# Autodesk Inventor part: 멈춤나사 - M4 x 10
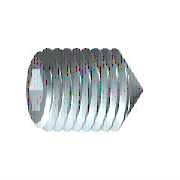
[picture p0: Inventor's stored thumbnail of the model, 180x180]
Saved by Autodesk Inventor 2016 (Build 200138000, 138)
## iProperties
Created: 2012-02
Part Number: 멈춤나사 - M4 x 10
Material: 강철, 연강
Description: 6각 소켓 머리 없는 멈춤 나사
Document SubType Name: Modeling
Standard: KS B 1028
Designer: mduedu
Standards Organization: KS
Language: ko-KR
Size Designation: 원추점 M4x10
Categories: <MemberInstance><Categories><Category DisplayName="조임쇠" InternalName="e4da775c-781d-43d5-af7c-5136215cf5a6" Mnemonic="FSTN"><Category DisplayName="볼트" InternalN
Density: 7.86 g/cm^3
Mass: 0.792069 g
Surface Area: 1.48192 cm^2
Volume: 0.100772 cm^3
Appearance: 강철
Author: mduedu
IsCustomPart: 1
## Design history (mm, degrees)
sketch "스케치1"
  geometry: L1 (0, 0)-(6.833, 0); L2 (10, 1.155)-(10, 2); L3 (10, 2)-(0, 2); L4 (10, 1.155)-(7.5, 1.155); L5 (7.5, 1.155)-(6.833, 0); L6 (0, -0.4)-(0, 2.4) reference; L7 (0, 2)-(0, 0)
  constraints: 13 end point, 3 parallel, 1 collinear, 1 perpendicular, 1 point on line
  dimensions: "d0" = 2.5 distance of L2.start L4.end (= INTI); "d1" = 60 deg angle of L5 L1; "d2" = 4 diameter of L3 L1 (= NND); "d3" = 2.3094 diameter of L4 L1 (= 1.1547 x SW); "d5" = 10 distance from line of L2 L3.end (= NLG)
revolve "본체" sketch "스케치1" stored, may be unused: angle "d6" = 90 deg
sketch "스케치2"
  geometry: L1 (-0.577, 1)-(0.577, 1); L2 (0.577, 1)-(1.155, 0); L3 (1.155, 0)-(0.577, -1); L4 (0.577, -1)-(-0.577, -1); L5 (-0.577, -1)-(-1.155, 0); L6 (-1.155, 0)-(-0.577, 1); 3 further points
  constraints: 12 end point, 1 coincident, 1 horizontal, 13 other
extrude "슬롯" join sketch "스케치2" taper "d7" = 0 deg; stored distance "d21" = 10
workaxis "Work Axis1"
workplane "Work Plane1"
sketch "스케치4"
  geometry: L1 (-5, 0.2)-(-3.2, 2) reference; L2 (-5, -0.2)-(-3.2, -2) reference; L3 (-3.2, 2)-(-5.2, 0); L4 (-3.2, -2)-(-5.2, 0); 2 further points
  constraints: 4 end point, 2 collinear, 1 coincident
body "Solid1"
feature "스레드" dims "d12" = 10 (= NLG), "d13" = 0
chamfer "모따기1" distance "d8" = 1.8 (computed from NND, SPD, FAWI); stored, may be unused: angle "d9" = 45 deg (= FAWI), second distance "d34" = 1.8 (computed from NND, SPD, FAWI)
chamfer "모따기2" distance "d10" = 0.42941 (= -0.5 x GD1 + 0.5 x NND); stored, may be unused: angle "d11" = 45 deg (= FAWI), second distance "d35" = 0.42941 (= -0.5 x GD1 + 0.5 x NND)
other parameters: "NND" = 4 [user parameter; used in 5 equation terms], "NLG" = 10 [user parameter; used in 2 equation terms], "INTI" = 2.5 [user parameter; used in 1 equation term], "FAWI" = 45 deg [user parameter; used in 4 equation terms], "SW" = 2 [user parameter; used in 2 equation terms], "GD1" = 3.14117 (= THREADDIA - 1.2269 x PTC) [user parameter; used in 2 equation terms], "d4" = 0, "FAWI1" = 45 deg [user parameter], "SPD" = 0.4 [user parameter; used in 2 equation terms], "d36" = 0, "d37" = 0, "GUL" = 0.42941 (= 0.61345 x PTC) [user parameter], "TPU" = 14.28571 (computed from PTC) [user parameter], "TOA" = 30 deg [user parameter], "THREADDIA" = 4 [user parameter; used in 1 equation term], "PTC" = 0.7 [user parameter; used in 4 equation terms], "GAL" = 0.42941 (= 0.61345 x PTC) [user parameter], "E0" = 2.31 (= 1.155 x SW) [user parameter]
